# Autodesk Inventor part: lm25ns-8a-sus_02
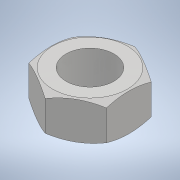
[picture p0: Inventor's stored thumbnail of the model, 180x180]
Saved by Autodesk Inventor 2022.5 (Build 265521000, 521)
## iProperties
Part Number: lm25ns-8a-sus_02
Material: 一般
Document SubType Name: Modeling
Designer: ImaoCorp
Density: 1 g/cm^3
Appearance: 既定
Author: ImaoCorp
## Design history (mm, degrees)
feature "lm25ns-8a-sus_02"
node "ソリッド1"
